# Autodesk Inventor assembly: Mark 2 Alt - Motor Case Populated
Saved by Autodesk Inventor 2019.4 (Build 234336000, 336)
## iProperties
Created: 2020-06
Part Number: Mark 2 Alt - Motor Case Populated
Document SubType Name: Assembly
Designer: Administrator
Title: Mark 2 Alt - Motor Case Populated v1
Author: Administrator
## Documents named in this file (2)
- c:\worker\convert-fusion-r04\tmp\job-1\512\output\files\f77988fd-7a05-4e23-8144-3385e7c42af4\8c4ada3f-5057-4ade-b3d8-f0f6a88938cf.iam
- c:\worker\convert-fusion-r04\tmp\job-1\512\output\files\f77988fd-7a05-4e23-8144-3385e7c42af4\Mark 2 Alt - Motor Case Populated v1.ipt
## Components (1 placed, 1 different names)
1. Mark 2 Alt - Motor Case Populated v1
